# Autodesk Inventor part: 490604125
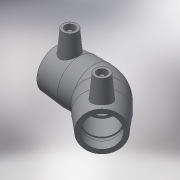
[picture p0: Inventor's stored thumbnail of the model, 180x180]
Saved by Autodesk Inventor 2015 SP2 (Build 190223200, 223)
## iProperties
Created: 2017-06
Part Number: 490604125
Material: Generic
Description: PLASSON 45° ELBOW 125
Document SubType Name: Modeling
Designer: KIM
Mass: 55.0731 g
Surface Area: 148.067 cm^2
Volume: 55.0731 cm^3
Density: 1 g/cm^3
Appearance: Default
Author: KIM
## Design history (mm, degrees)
derived "490604.ipt"
feature "Solid1::490604.ipt"
tag "TaggingFeature1"
body "Solid1"
other parameters: "d2" = 165, "d4" = 76, "d5" = 148.5, "d8" = 168 deg, "d10" = 34.4, "d11" = 11.46667, "d14" = 17.6296, "d18" = 125, "d19" = 3.52592, "d20" = 168 deg, "d22" = 151.8, "d23" = 165, "d24" = 147.246, "d29" = 88, "d30" = 15, "d31" = 106.4, "d34" = 5 deg, "d35" = 12, "d39" = 0, "d41" = 4, "d42" = 14, "d43" = 0, "d44" = 9.6, "d45" = 4.8, "d46" = 6, "d47" = 0, "d49" = 125, "d50" = 106.25, "d51" = 34.4, "d52" = 86, "d54" = 135 deg, "d65" = 125, "d67" = 45 deg, "d71" = 135 deg, "d75" = 8.25, "d82" = 45 deg, "d83" = 86, "d84" = 148.5, "d86" = 74.25, "d87" = 135 deg, "d88" = 304, "d90" = 86, "d91" = 0, "d92" = 86, "d93" = 0, "d94" = 135 deg, "d95" = 75.9, "d98" = 304, "d99" = 97.28, "d101" = 3, "d102" = 0, "d103" = 3, "d104" = 0, "d105" = 24.94, "d106" = 6.235, "d_" = 125, "L_" = 304, "L_1" = 86, "D_" = 165, "A_" = 88, "d_2" = 12
